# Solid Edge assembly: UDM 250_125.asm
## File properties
Title: Zylinder
Author: ahadarics
Template: iso assembly.asm
Last saved by: ahadarics
Revision: 32
Application: Solid Edge
Username: ahadarics
Dokumentum tartalom típus: 1
Document Number: UDM 250/125
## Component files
Kit_1.par
Profilrohr 250_125.par
Zugstange 250_125.par
Kit_2.par
Mutter.par
Kolbenstange 250_125.par
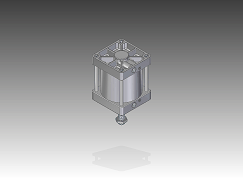
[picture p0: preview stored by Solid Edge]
